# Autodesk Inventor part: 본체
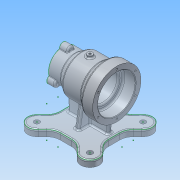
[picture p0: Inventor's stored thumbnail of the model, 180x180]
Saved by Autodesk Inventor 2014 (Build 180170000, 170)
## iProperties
Created: 2017-03
Part Number: 본체
Material: 알루미늄 6061
Document SubType Name: Modeling
Designer: NET
Density: 2.71 g/cm^3
Appearance: 알루미늄 - 평지
Mass: 1008.03 g
Surface Area: 842.186 cm^2
Volume: 371.969 cm^3
Author: NET
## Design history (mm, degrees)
sketch "스케치1"
  geometry: L1 (-45, 45)-(45, 45); L2 (45, 45)-(45, -45); L3 (45, -45)-(-45, -45); L4 (-45, -45)-(-45, 45); L5 (-12.021, 12.021)-(-49.497, 49.497); L6 (0, 0)-(-49.497, -49.497); L7 (0, 0)-(-38.765, 0); L8 (-24.042, 0)-(-61.518, -37.477); L9 (0, -24.042)-(-37.477, -61.518); L10 (-24.042, 0)-(-73.539, 49.497); L11 (0, 24.042)-(-49.497, 73.539); L12 (12.021, -12.021)-(49.497, -49.497); L13 (0, 0)-(49.497, 49.497); L14 (24.042, 0)-(73.539, -49.497); L15 (0, -24.042)-(49.497, -73.539); L16 (0, 24.042)-(37.477, 61.518); L17 (24.042, 0)-(61.518, 37.477); C1 r 17 at (-49.497, 49.497); C2 r 17 at (-49.497, -49.497); C3 r 17 at (49.497, 49.497); C4 r 17 at (49.497, -49.497); C5 r 70 at (0, 0); A1 r 70 centre (0, 0) between (-60.036, -35.995) and (-35.995, -60.036); A2 r 70 centre (0, 0) between (35.995, -60.036) and (60.036, -35.995); A3 r 70 centre (0, 0) between (60.036, 35.995) and (35.995, 60.036); A4 r 70 centre (0, 0) between (-35.995, 60.036) and (-60.036, 35.995); A5 r 25 centre (-70, 10.603) between (-45, 10.603) and (-52.322, 28.281); A6 r 25 centre (-70, -10.603) between (-52.322, -28.281) and (-45, -10.603); A7 r 25 centre (-10.603, -70) between (-10.603, -45) and (-28.281, -52.322); A8 r 25 centre (10.603, -70) between (28.281, -52.322) and (10.603, -45); A9 r 25 centre (70, 10.603) between (52.322, 28.281) and (45, 10.603); A10 r 25 centre (70, -10.603) between (45, -10.603) and (52.322, -28.281); A11 r 25 centre (-10.603, 70) between (-28.281, 52.322) and (-10.603, 45); A12 r 25 centre (10.603, 70) between (10.603, 45) and (28.281, 52.322); 3 further points
  constraints: 34 end point, 29 point on circle, 25 point on line, 17 centre point, 16 tangent, 10 parallel, 5 coincident, 2 midpoint, 2 perpendicular, 1 horizontal, 1 horizontal alignment, 1 vertical alignment
  dimensions: "d0" = 90 distance of L1.start L1.end; "d1" = 90 distance of L1.end L2.end; "d3" = 45 deg angle of L7 L5; "d4" = 45 deg angle of L6 L7; "d5" = 34 diameter of C1; "d6" = 34 diameter of C2; "d7" = 17 distance between parallel lines of L11 L5; "d8" = 17 distance between parallel lines of L5 L10; "d9" = 17 distance between parallel lines of L8 L6; "d10" = 17 distance between parallel lines of L9 L6; "d11" = 49.49747 horizontal distance of point (0, 0) C2.centre; "d12" = 45 deg angle of L7 L13; "d13" = 45 deg angle of L7 L12; "d14" = 34 diameter of C3; "d15" = 34 diameter of C4; "d16" = 17 distance between parallel lines of L16 L13; "d17" = 17 distance between parallel lines of L17 L13; "d18" = 17 distance between parallel lines of L14 L12; "d19" = 17 distance between parallel lines of L15 L12; "d20" = 49.49747 horizontal distance of point (0, 0) L5.end; "d21" = 70 distance from line of L12 L13.end; "d22" = 49.49747 horizontal distance of point (0, 0) L6.end; "d23" = 49.49747 horizontal distance of point (0, 0) C4.centre; "d26" = 50 diameter of A5; "d27" = 50 diameter of A6; "d28" = 50 diameter of A7; "d29" = 50 diameter of A8; "d30" = 50 diameter of A9; "d31" = 50 diameter of A10; "d32" = 50 diameter of A11; "d33" = 50 diameter of A12; "d34" = 25 radius of A5 (derived); "d35" = 70 distance of L9.start L15.end; "d36" = 70 distance of L14.start L14.end; "d37" = 70 distance of L12.start L17.end; "d38" = 70 distance of L5.start L16.end; "d39" = 70 distance of L11.start L11.end; "d40" = 70 distance of L8.start L10.end; "d41" = 70 distance of L5.start L8.end; "d42" = 70 distance of L12.start L9.end; "d43" = 70 distance of L6.start L13.end (derived); "d44" = 70 radius of A4 (derived); "d45" = 70 radius of A1 (derived); "d46" = 90 distance of L3.end L1.start (derived); "d47" = 12.02082 horizontal distance of L12.start point (0, 0); "d48" = 12.02082 horizontal distance of L12.start point (0, 0); "d49" = 12.02082 horizontal distance of L5.start point (0, 0); "d50" = 12.02082 horizontal distance of point (0, 0) L5.start (derived); "d51" = 24.04163 distance of point (0, 0) L8.start (derived); "d52" = 38.76502 distance of L6.start L7.end; "d188" = 140 diameter of C5
extrude "돌출1" new body sketch "스케치1" distance "d53" = 12; taper "d54" = 0 deg
sketch "스케치2"
  geometry: L1 (-50, 82)-(50, 82); L2 (10.603, 0)-(-10.603, 0) reference; L3 (-50, 82)-(-50, 127); L4 (-50, 127)-(-30, 127); L5 (-30, 127)-(-19, 118); L6 (-19, 118)-(15, 118); L7 (15, 118)-(27, 109.5); L8 (27, 109.5)-(50, 109.5); L9 (50, 109.5)-(50, 82); L10 (-50, 117)-(-27, 117); L11 (-27, 117)-(-27, 108); L12 (-27, 108)-(20, 108); L13 (20, 108)-(20, 99.5); L14 (20, 99.5)-(50, 99.5); 3 further points
  constraints: 26 end point, 5 parallel, 5 perpendicular, 2 midpoint, 2 point on line, 1 horizontal, 1 vertical alignment
  dimensions: "d55" = 100 distance of L1.start L1.end; "d56" = 82 vertical distance of point (0, 0) L1.start; "d57" = 90 diameter of L4 L1; "d58" = 72 diameter of L6 L1; "d59" = 55 diameter of L8 L1; "d60" = 20 distance of L3.end L4.end; "d61" = 31 horizontal distance of L5.end L3.end; "d62" = 65 horizontal distance of L6.end L3.end; "d63" = 23 distance of L7.end L8.end; "d64" = 23 distance of L10.start L10.end; "d65" = 47 distance of L11.end L12.end; "d67" = 70 diameter of L10 L1; "d68" = 52 diameter of L12 L1; "d69" = 35 diameter of L14 L1
revolve "회전1" stored, may be unused: angle "d70" = 90 deg
sketch "스케치3"
  geometry: L1 (10.603, 0)-(-10.603, 0) reference; L2 (10.603, 12)-(-10.603, 12) reference; L3 (0, 12)-(-37, 12); L4 (-37, 12)-(-37, 72); L5 (-37, 72)-(37, 72); L6 (37, 72)-(37, 12); L7 (37, 12)-(0, 12); 1 further point
  constraints: 10 end point, 2 perpendicular, 2 point on line, 1 collinear, 1 midpoint, 1 parallel
  dimensions: "d71" = 37 distance of L3.end L3.start; "d72" = 37 distance of L6.end L3.start; "d73" = 60 distance of L3.end L4.end
extrude "돌출2" join sketch "스케치3" stored distance "d74" = 8; taper "d75" = 0 deg
sketch "스케치4"
  geometry: L1 (10.603, 0)-(-10.603, 0) reference; L2 (4, 12)-(4, 54.792) reference; L3 (-4, 12)-(4, 12) reference; L4 (-4, 54.792)-(-4, 12) reference; L5 (0, 12)-(-25, 12); L6 (-25, 12)-(-15.302, 67); L7 (-15.302, 67)-(0, 67); L8 (0, 67)-(0, 12); L9 (0, 12)-(25, 12); L10 (25, 12)-(15.302, 67); L11 (15.302, 67)-(0, 67); L12 (-36.106, 12)-(-66.497, 12) reference; L13 (35.995, 12)-(28.281, 12) reference; A1 r 27.5 centre (0, 82) between (-4, 54.792) and (4, 54.792) reference; 2 further points
  constraints: 14 end point, 3 perpendicular, 2 parallel, 1 midpoint
  dimensions: "d76" = 25 distance of L5.start L5.end; "d77" = 25 distance of L5.start L9.end; "d78" = 100 deg angle of L6 L12; "d79" = 100 deg angle of L13 L10; "d80" = 55 distance of L7.end L5.start; "d81" = 15.30202 distance of L6.end L7.end (derived)
extrude "돌출3" join sketch "스케치4" stored distance "d82" = 8; taper "d83" = 0 deg
revolve "회전2" stored, may be unused: angle "d84" = 90 deg
sketch "스케치5"
  geometry: L1 (-107.4, 0)-(70.4, 0) reference; C1 r 7 at (27.5, 0); 2 further points
  constraints: 1 centre point, 1 horizontal alignment, 1 point on line, 1 other
  dimensions: "d85" = 14 diameter of C1
extrude "돌출4" join sketch "스케치5" distance "d86" = 15; taper "d87" = 0 deg
sketch "스케치6"
  geometry: C1 r 35 at (0, 0) reference; 2 further points
  constraints: 1 horizontal alignment
  dimensions: "d91" = 40 distance of C1.centre point (-40, 0)
hole "구멍1" sketch "스케치6" at (-40, 0) diameter "d92" = 3.242; stored, may be unused: countersink angle "d96" = 90 deg, drill point angle "d98" = 118 deg; dims "d93" = 9, "d94" = 4, "d95" = 2, "d97" = 11
sketch "스케치7"
  geometry: C1 r 17.5 at (-27.5, 0) reference; A1 r 27.5 centre (-27.5, 0) between (-34.792, -26.516) and (-0.891, -6.943) reference; A2 r 7 centre (0, 0) between (-0.891, -6.943) and (-0.891, 6.943) reference; A3 r 27.5 centre (-27.5, 0) between (-0.891, 6.943) and (-34.792, 26.516) reference; A4 r 7 centre (-41.25, 23.816) between (-34.792, 26.516) and (-46.817, 19.573) reference; A5 r 27.5 centre (-27.5, 0) between (-46.817, 19.573) and (-46.817, -19.573) reference; A6 r 7 centre (-41.25, -23.816) between (-46.817, -19.573) and (-34.792, -26.516) reference; 1 further point
hole "구멍2" diameter "d104" = 3.242; stored, may be unused: countersink angle "d108" = 90 deg, drill point angle "d110" = 118 deg; dims "d102" = 10, "d103" = 10, "d105" = 9, "d106" = 4, "d107" = 2, "d109" = 11
node "작업 평면1"
sketch "스케치8"
  geometry: L1 (4, 4)-(4, 18.14) reference; L2 (4, 18.14)-(-4, 18.14) reference; L3 (-4, 18.14)-(-4, 4) reference; L4 (-4, 4)-(-15, 4) reference; L5 (-15, -4)-(-15, 4) reference; L6 (-15, -4)-(-4, -4) reference; L7 (-4, -4)-(-4, -18.14) reference; L8 (-4, -18.14)-(4, -18.14) reference; L9 (4, -18.14)-(4, -4) reference; L10 (4, -4)-(19, -4) reference; L11 (19, -4)-(19, 4) reference; L12 (19, 4)-(4, 4) reference; L13 (50, 45)-(50, -45) reference; C1 r 5 at (0, 0); 1 further point
  constraints: 1 centre point, 1 coincident
  dimensions: "d115" = 10 diameter of C1; "d116" = 50 distance from line of C1.centre L13 (derived)
extrude "돌출5" join sketch "스케치8" stored distance "d117" = 15; taper "d118" = 0 deg
hole "구멍3" diameter "d121" = 4.134; stored, may be unused: countersink angle "d125" = 90 deg, drill point angle "d127" = 118 deg; dims "d119" = 10, "d120" = 10, "d122" = 9, "d123" = 4, "d124" = 2, "d126" = 32.25
chamfer "모따기1" distance "d128" = 1; stored, may be unused: second distance "d129" = 2, angle "d130" = 45 deg
chamfer "모따기2" distance "d131" = 1; stored, may be unused: second distance "d132" = 2, angle "d133" = 45 deg
fillet "모깎기1" dims "d134" = 3
fillet "모깎기2" dims "d135" = 3
fillet "모깎기3" dims "d136" = 3
fillet "모깎기4" dims "d137" = 1
fillet "모깎기5" dims "d138" = 3
fillet "모깎기6" dims "d139" = 1
fillet "모깎기7" dims "d140" = 3
fillet "모깎기8" dims "d141" = 1
sketch "스케치9"
  geometry: L1 (4, 25)-(4, 4) reference; L2 (4, 4)-(37, 4) reference; L3 (37, 4)-(37, -4) reference; L4 (37, -4)-(4, -4) reference; L5 (4, -4)-(4, -25) reference; L6 (4, -25)-(-4, -25) reference; L7 (-4, -25)-(-4, -4) reference; L8 (-4, -4)-(-37, -4) reference; L9 (-37, -4)-(-37, 4) reference; L10 (-37, 4)-(-4, 4) reference; L11 (-4, 4)-(-4, 25) reference; L12 (-4, 25)-(4, 25) reference; L13 (35.995, 60.036)-(28.281, 52.322) reference; L14 (10.603, 45)-(-10.603, 45) reference; L15 (-28.281, 52.322)-(-35.995, 60.036) reference; L16 (-60.036, 35.995)-(-52.322, 28.281) reference; L17 (-45, 10.603)-(-45, -10.603) reference; L18 (-52.322, -28.281)-(-60.036, -35.995) reference; L19 (-35.995, -60.036)-(-28.281, -52.322) reference; L20 (-10.603, -45)-(10.603, -45) reference; L21 (28.281, -52.322)-(35.995, -60.036) reference; L22 (60.036, -35.995)-(52.322, -28.281) reference; L23 (45, -10.603)-(45, 10.603) reference; L24 (52.322, 28.281)-(60.036, 35.995) reference; A1 r 70 centre (0, 0) between (36.106, 59.97) and (35.995, 60.036) reference; A2 r 25 centre (10.603, 70) between (10.603, 45) and (28.281, 52.322) reference; A3 r 25 centre (-10.603, 70) between (-28.281, 52.322) and (-10.603, 45) reference; A4 r 70 centre (0, 0) between (-35.995, 60.036) and (-36.106, 59.97) reference; A5 r 17 centre (-49.497, 49.497) between (-36.106, 59.97) and (-59.97, 36.106) reference; A6 r 70 centre (0, 0) between (-59.97, 36.106) and (-60.036, 35.995) reference; A7 r 25 centre (-70, 10.603) between (-45, 10.603) and (-52.322, 28.281) reference; A8 r 25 centre (-70, -10.603) between (-52.322, -28.281) and (-45, -10.603) reference; A9 r 70 centre (0, 0) between (-60.036, -35.995) and (-59.97, -36.106) reference; A10 r 17 centre (-49.497, -49.497) between (-59.97, -36.106) and (-36.106, -59.97) reference; A11 r 70 centre (0, 0) between (-36.106, -59.97) and (-35.995, -60.036) reference; A12 r 25 centre (-10.603, -70) between (-10.603, -45) and (-28.281, -52.322) reference; A13 r 25 centre (10.603, -70) between (28.281, -52.322) and (10.603, -45) reference; A14 r 70 centre (0, 0) between (35.995, -60.036) and (36.106, -59.97) reference; A15 r 17 centre (49.497, -49.497) between (36.106, -59.97) and (59.97, -36.106) reference; A16 r 70 centre (0, 0) between (59.97, -36.106) and (60.036, -35.995) reference; A17 r 25 centre (70, -10.603) between (45, -10.603) and (52.322, -28.281) reference; A18 r 25 centre (70, 10.603) between (52.322, 28.281) and (45, 10.603) reference; A19 r 70 centre (0, 0) between (60.036, 35.995) and (59.97, 36.106) reference; A20 r 17 centre (49.497, 49.497) between (59.97, 36.106) and (36.106, 59.97) reference
hole "구멍4" diameter "d144" = 10; stored, may be unused: countersink angle "d148" = 90 deg, drill point angle "d150" = 0 deg; dims "d142" = 10, "d143" = 10, "d145" = 9, "d146" = 4, "d147" = 2, "d149" = 32.25
hole "구멍5" diameter "d153" = 10; stored, may be unused: countersink angle "d157" = 90 deg, drill point angle "d159" = 0 deg; dims "d151" = 10, "d152" = 10, "d154" = 9, "d155" = 4, "d156" = 2, "d158" = 32.25
hole "구멍6" diameter "d162" = 10; stored, may be unused: countersink angle "d166" = 90 deg, drill point angle "d168" = 0 deg; dims "d160" = 10, "d161" = 10, "d163" = 9, "d164" = 4, "d165" = 2, "d167" = 32.25
hole "구멍7" diameter "d171" = 10; stored, may be unused: countersink angle "d175" = 90 deg, drill point angle "d177" = 0 deg; dims "d169" = 10, "d170" = 10, "d172" = 9, "d173" = 4, "d174" = 2, "d176" = 32.25
fillet "모깎기9" dims "d178" = 3
fillet "모깎기10" dims "d179" = 3
fillet "모깎기11" dims "d180" = 3
fillet "모깎기12" dims "d181" = 3
fillet "모깎기13" dims "d182" = 3
fillet "모깎기14" dims "d183" = 3
sketch "스케치11"
  geometry: L1 (-45, 10.603)-(-45, -10.603) reference; A1 r 70 centre (0, 0) between (58.397, 38.598) and (58.357, 38.658) reference; 1 further point
  constraints: 1 other
  dimensions: "d184" = 35 distance of point (0, 35) A1.centre; "d185" = 45 distance from line of L1 point (0, 35)
feature "엠보싱1" sketch "스케치11" dims "d0" = 90, "d1" = 90, "d3" = 45 deg, "d4" = 45 deg, "d5" = 34, "d6" = 34, "d7" = 17, "d8" = 17, "d9" = 17, "d10" = 17, "d11" = 49.49747, "d12" = 45 deg, "d13" = 45 deg, "d14" = 34, "d15" = 34, "d16" = 17, "d17" = 17, "d18" = 17, "d19" = 17, "d20" = 49.49747, "d21" = 70, "d22" = 49.49747, "d23" = 49.49747, "d26" = 50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
node "솔리드1"
pattern_circular "원형 패턴1" dims angle "d89" = 360 deg
pattern_circular "원형 패턴2" dims angle "d100" = 360 deg
pattern_circular "원형 패턴3" dims angle "d112" = 360 deg
node "투영된 루프1"
node "투영된 루프2"
other parameters: "d114" = -122
